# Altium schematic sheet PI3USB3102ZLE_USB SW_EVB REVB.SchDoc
size 386 x 246 mm
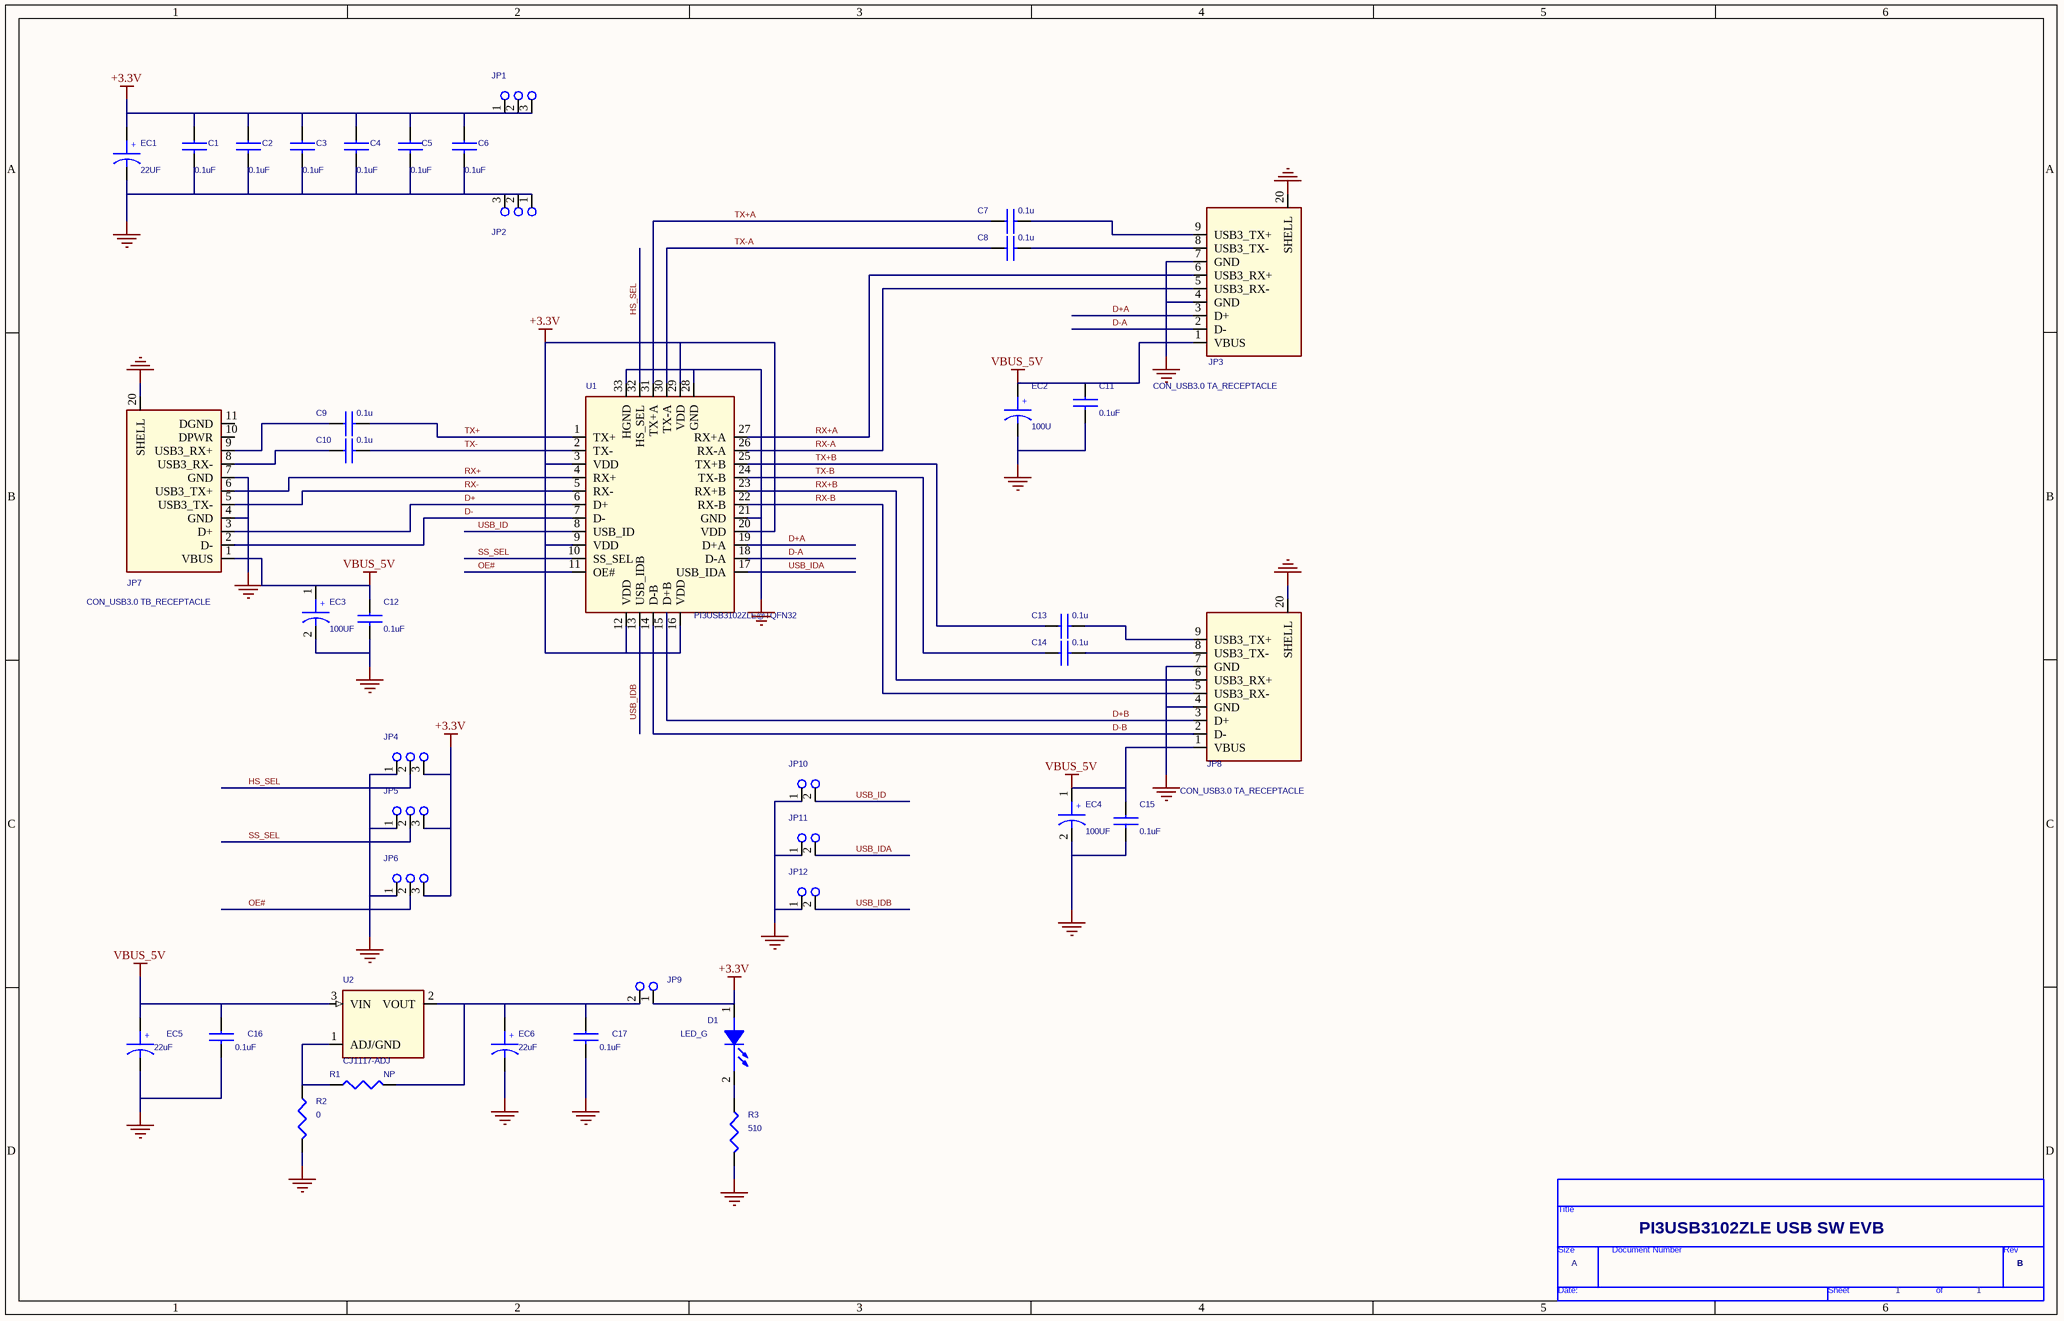
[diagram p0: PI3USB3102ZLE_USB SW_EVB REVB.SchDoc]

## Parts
*  Page Count: 1  Page Size: A  Title: PI3USB3102ZLE USB SW EVB  RevCode: B  (hidden comment: TitleBlock0)  (graphical)
C1  0.1uF  [CAP@CC_0402]
C2  0.1uF  [CAP@CC_0402]
C3  0.1uF  [CAP@CC_0402]
C4  0.1uF  [CAP@CC_0402]
C5  0.1uF  [CAP@CC_0402]
C6  0.1uF  [CAP@CC_0402]
C7  0.1u  [CC_0402]
C8  0.1u  [CC_0402]
C9  0.1u  [CC_0402]
C10  0.1u  [CC_0402]
C11  0.1uF  [CC_0402]
C12  0.1uF  [CAP@CC_0402]
C13  0.1u  [CC_0402]
C14  0.1u  [CC_0402]
C15  0.1uF  [CAP@CC_0402]
C16  0.1uF  [CC_0402]
C17  0.1uF  [CC_0402]
D1  LED_G  [LED_0805]
EC1  22UF  [CAP@CT_3528]
EC2  100U  [CT_7343]
EC3  100UF  [CAP@CT_7343]
EC4  100UF  [CAP@CT_7343]
EC5  22uF  [CT_3528]
EC6  22uF  [CT_3528]
JP1  3x1 Pin Header  [3x1 Pin Header]  (value not drawn)
JP2  3x1 Pin Header  [3x1 Pin Header]  (value not drawn)
JP3  CON_USB3.0 TA_RECEPTACLE  [CON_USB3.0 TA_RECEPTACLE]
JP4  3x1 Pin Header  [3x1 Pin Header]  (value not drawn)
JP5  3x1 Pin Header  [3x1 Pin Header]  (value not drawn)
JP6  3x1 Pin Header  [3x1 Pin Header]  (value not drawn)
JP7  CON_USB3.0 TB_RECEPTACLE  [CON_USB3.0 TB_RECEPTACLE]
JP8  CON_USB3.0 TA_RECEPTACLE  [CON_USB3.0 TA_RECEPTACLE]
JP9  2x1 Pin Header  [2x1 Pin Header]  (value not drawn)
JP10  2x1 Pin Header  [2x1 Pin Header]  (value not drawn)
JP11  2x1 Pin Header  [2x1 Pin Header]  (value not drawn)
JP12  2x1 Pin Header  [2x1 Pin Header]  (value not drawn)
R1  NP  [R_0402]
R2  0  [R_0402]
R3  510  [R_0402]
U1  PI3USB3102ZLE@TQFN32  [TQFN32_3X6]
U2  CJ1117-ADJ  [Pow_SOT_89]

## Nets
+3.3V: C1.1 C2.1 C3.1 C4.1 C5.1 C6.1 D1.1(ANODE) EC1.1 JP1.1 JP1.2 JP1.3 JP4.3 JP5.3 JP6.3 JP9.1 U1.3(VDD) U1.9(VDD) U1.12(VDD) U1.16(VDD) U1.20(VDD) U1.29(VDD)
GND: C1.2 C2.2 C3.2 C4.2 C5.2 C6.2 C11.2 C12.2 C15.2 C16.2 C17.2 EC1.2 EC2.2 EC3.2 EC4.2 EC5.2 EC6.2 JP2.1 JP2.2 JP2.3 JP3.4(GND) JP3.7(GND) JP3.20(SHELL) JP4.1 JP5.1 JP6.1 JP7.4(GND) JP7.7(GND) JP7.20(SHELL) JP8.4(GND) JP8.7(GND) JP8.20(SHELL) JP10.1 JP11.1 JP12.1 R2.2 R3.2 U1.21(GND) U1.28(GND) U1.33(HGND)
VBUS_5V: C11.1 C12.1 C15.1 C16.1 EC2.1 EC3.1 EC4.1 EC5.1 JP3.1(VBUS) JP7.1(VBUS) JP8.1(VBUS) U2.3(VIN)
D+: JP7.3(D+) U1.6(D+)
D+A: JP3.3(D+) U1.19(D+A)
D+B: JP8.3(D+) U1.15(D+B)
D-: JP7.2(D-) U1.7(D-)
D-A: JP3.2(D-) U1.18(D-A)
D-B: JP8.2(D-) U1.14(D-B)
HS_SEL: JP4.2 U1.32(HS_SEL)
OE#: JP6.2 U1.11(OE#)
RX+: JP7.6(USB3_TX+) U1.4(RX+)
RX+A: JP3.6(USB3_RX+) U1.27(RX+A)
RX+B: JP8.6(USB3_RX+) U1.23(RX+B)
RX-: JP7.5(USB3_TX-) U1.5(RX-)
RX-A: JP3.5(USB3_RX-) U1.26(RX-A)
RX-B: JP8.5(USB3_RX-) U1.22(RX-B)
SS_SEL: JP5.2 U1.10(SS_SEL)
TX+: C9.2 U1.1(TX+)
TX+A: C7.1 U1.31(TX+A)
TX+B: C13.1 U1.25(TX+B)
TX-: C10.2 U1.2(TX-)
TX-A: C8.1 U1.30(TX-A)
TX-B: C14.1 U1.24(TX-B)
USB_ID: JP10.2 U1.8(USB_ID)
USB_IDA: JP11.2 U1.17(USB_IDA)
USB_IDB: JP12.2 U1.13(USB_IDB)
NetC7_2: C7.2 JP3.9(USB3_TX+)
NetC8_2: C8.2 JP3.8(USB3_TX-)
NetC9_1: C9.1 JP7.9(USB3_RX+)
NetC10_1: C10.1 JP7.8(USB3_RX-)
NetC13_2: C13.2 JP8.9(USB3_TX+)
NetC14_2: C14.2 JP8.8(USB3_TX-)
NetC17_1: C17.1 EC6.1 JP9.2 R1.2 U2.2(VOUT)
NetD1_2: D1.2(CATHODE) R3.1
NetR1_1: R1.1 R2.1 U2.1(ADJ/GND)

Not connected (* = marked no-connect by the designer): JP7 10(DPWR) 11(DGND)

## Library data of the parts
C1-C6 C12 C15 = 0.01UF 0402
C7-C10 C13 C14 = C_0.1u_0402_Dup1
C11 = C_0.1u_0402_Dup2
C16 C17 = C_0.1u_0402
D1 = LED_0805_G
EC1 = 22UF 3528
EC2 = C_tan_100u_7343
EC3 EC4 = 100UF 7343
EC5 EC6 = C_tan_22u_3528
JP9 = 2x1 Pin Header_Dup1
R1-R3 = R_0402
U2 = Pow_LDO_ADJ_0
